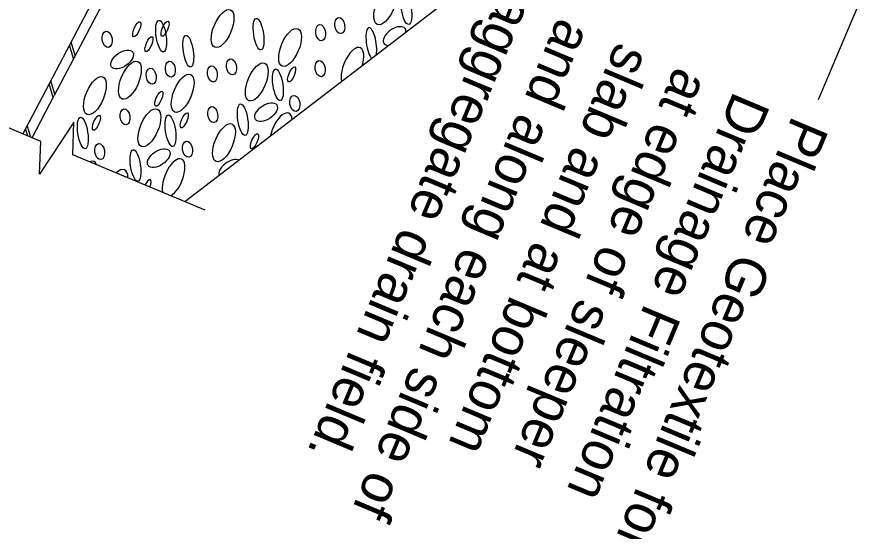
# Model space of a CAD drawing. Extents: x 1968564 to 1968711, y 796599 to 796794.
# Drawn here: x 1968598.8 to 1968609.43, y 796684.77 to 796691.24 of the extents above; entities that cross this region are included whole.
import ezdxf

# ---------------------------------------------------------------- set-up
doc = ezdxf.new("R2010")
doc.units = 0
for name, color, linetype in [('BR_AUTO DIMENSION', 7, 'Continuous'), ('BR_DETAILS', 7, 'Continuous'), ('BR_GROUND LINES', 7, 'Continuous'), ('BR_STRUCTURAL STEEL', 7, 'Continuous'), ('BR_TEXT', 7, 'Continuous')]:
    doc.layers.add(name, color=color, linetype=linetype)

msp = doc.modelspace()

# ---------------------------------------------------------------- linework, layer by layer
at = {"layer": 'BR_AUTO DIMENSION'}
msp.add_line((1968609.432, 796691.479), (1968608.892, 796690.193), dxfattribs=at)
at = {"layer": 'BR_DETAILS'}
for p, q in [((1968599.107, 796689.67), (1968597.68, 796690.268)), ((1968601.175, 796688.803), (1968599.507, 796689.502))]:
    msp.add_line(p, q, dxfattribs=at)
msp.add_lwpolyline([(1968599.507, 796689.502), (1968599.523, 796689.914), (1968599.091, 796689.258), (1968599.107, 796689.67)], dxfattribs=at)
at = {"layer": 'BR_GROUND LINES'}
msp.add_line((1968607.048, 796693.608), (1968600.919, 796688.91), dxfattribs=at)
for centre, major_axis, ratio in [((1968603.441, 796691.378), (0.099, 0.236), 0.439024), ((1968603.707, 796691.341), (-0.03, 0.199), 0.307583), ((1968601.394, 796691.091), (0.099, 0.236), 0.439024), ((1968600.314, 796691.083), (0.0396, 0.0944), 0.335809), ((1968600.62, 796690.995), (-0.03, 0.199), 0.307583), ((1968600.669, 796691.089), (0.0396, 0.0944), 0.335809), ((1968601.847, 796691.02), (-0.03, 0.199), 0.307583), ((1968602.628, 796691.039), (-0.015, 0.101), 0.604846), ((1968602.869, 796691.128), (-0.015, 0.101), 0.604846), ((1968599.941, 796690.955), (-0.015, 0.101), 0.604846), ((1968602.243, 796690.853), (0.099, 0.236), 0.439024), ((1968600.466, 796690.894), (0.0396, 0.0944), 0.335809), ((1968600.962, 796690.806), (-0.03, 0.199), 0.307583), ((1968600.13, 796690.702), (0.134, 0.093), 0.55), ((1968601.506, 796690.608), (-0.015, 0.101), 0.604846), ((1968600.227, 796690.44), (0.099, 0.236), 0.439024), ((1968600.736, 796690.579), (-0.015, 0.101), 0.604846), ((1968601.265, 796690.519), (-0.015, 0.101), 0.604846), ((1968601.824, 796690.419), (0.099, 0.236), 0.439024), ((1968602.263, 796690.513), (0.0396, 0.0944), 0.335809), ((1968602.622, 796690.586), (-0.015, 0.101), 0.604846), ((1968599.787, 796690.246), (0.099, 0.236), 0.439024), ((1968600.496, 796690.49), (-0.015, 0.101), 0.604846), ((1968600.891, 796690.276), (0.099, 0.236), 0.439024), ((1968602.09, 796690.383), (-0.03, 0.199), 0.307583), ((1968600.591, 796690.207), (0.0396, 0.0944), 0.335809), ((1968602.303, 796690.149), (-0.015, 0.101), 0.604846), ((1968600.166, 796689.979), (-0.015, 0.101), 0.604846), ((1968600.472, 796689.842), (0.099, 0.236), 0.439024), ((1968601.27, 796690.008), (-0.015, 0.101), 0.604846), ((1968601.648, 796689.944), (-0.03, 0.199), 0.307583), ((1968601.941, 796690.038), (0.134, 0.093), 0.55), ((1968599.634, 796689.776), (-0.03, 0.199), 0.307583), ((1968599.806, 796689.906), (0.0396, 0.0944), 0.335809), ((1968600.738, 796689.805), (-0.03, 0.199), 0.307583), ((1968600.911, 796689.935), (0.0396, 0.0944), 0.335809), ((1968601.411, 796689.654), (0.099, 0.236), 0.439024), ((1968601.795, 796689.672), (0.0396, 0.0944), 0.335809), ((1968600.952, 796689.572), (-0.015, 0.101), 0.604846), ((1968599.847, 796689.542), (-0.015, 0.101), 0.604846), ((1968600.297, 796689.367), (-0.03, 0.199), 0.307583), ((1968600.59, 796689.46), (0.134, 0.093), 0.55)]:
    msp.add_ellipse(centre, major_axis=major_axis, ratio=ratio, dxfattribs=at)
for centre, major_axis, ratio, start_param, end_param in [((1968603.266, 796690.903), (-0.03, 0.199), 0.307583, 3.842622, 9.060911), ((1968603.559, 796690.996), (0.134, 0.093), 0.55, 5.780492, 10.098048), ((1968603.028, 796690.613), (0.099, 0.236), 0.439024, 4.92773, 8.947519), ((1968602.129, 796689.79), (0.099, 0.236), 0.439024, 5.60658, 8.268668), ((1968600.777, 796689.212), (0.099, 0.236), 0.439024, 3.64943, 8.916941), ((1968601.488, 796689.324), (0.134, 0.093), 0.55, 0.286212, 3.025957), ((1968599.673, 796689.183), (0.099, 0.236), 0.439024, 5.833235, 6.733136), ((1968600.059, 796689.077), (0.099, 0.236), 0.439024, 5.484616, 7.081755), ((1968600.443, 796689.095), (0.0396, 0.0944), 0.335809, 4.845535, 7.720836)]:
    msp.add_ellipse(centre, major_axis=major_axis, ratio=ratio, start_param=start_param, end_param=end_param, dxfattribs=at)
at = {"layer": 'BR_STRUCTURAL STEEL'}
for p, q in [((1968602.345, 796696.353), (1968599.164, 796690.308)), ((1968602.456, 796696.295), (1968599.275, 796690.249)), ((1968599.519, 796690.712), (1968599.466, 796690.881)), ((1968599.539, 796690.751), (1968599.487, 796690.92)), ((1968599.283, 796690.264), (1968599.23, 796690.433)), ((1968599.164, 796690.308), (1968598.879, 796689.766)), ((1968599.262, 796690.225), (1968599.21, 796690.394)), ((1968598.995, 796689.717), (1968599.275, 796690.249)), ((1968598.978, 796689.724), (1968598.933, 796689.869)), ((1968598.941, 796689.74), (1968598.913, 796689.83))]:
    msp.add_line(p, q, dxfattribs=at)

# ---------------------------------------------------------------- texts
at = {"layer": 'BR_TEXT'}
for s, p in [('aggregate drain field.', (1968604.882, 796691.556)), ('and along each side of ', (1968605.62, 796691.247)), ('slab and at bottom ', (1968606.357, 796690.937)), ('at edge of sleeper ', (1968607.095, 796690.628)), ('Drainage Filtration', (1968607.833, 796690.319)), ('Place Geotextile for ', (1968608.571, 796690.009))]:
    msp.add_text(s, height=0.49995, rotation=247.246, dxfattribs=at).set_placement(p)

doc.saveas('drawing.dxf')
